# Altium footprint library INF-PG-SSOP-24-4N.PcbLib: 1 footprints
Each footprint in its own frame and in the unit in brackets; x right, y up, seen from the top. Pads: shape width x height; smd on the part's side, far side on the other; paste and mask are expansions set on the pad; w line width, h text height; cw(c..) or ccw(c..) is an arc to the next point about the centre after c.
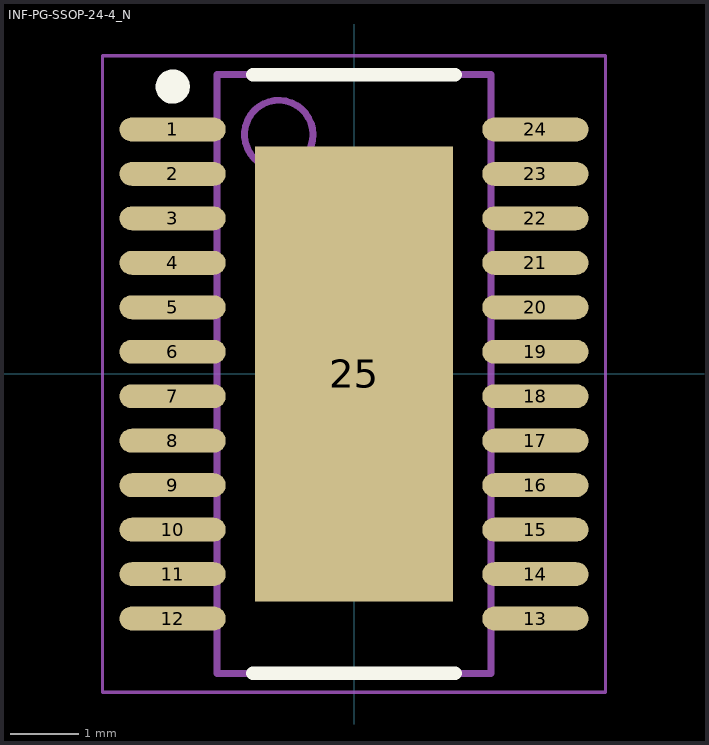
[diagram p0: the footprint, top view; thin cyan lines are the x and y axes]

## INF-PG-SSOP-24-4_N [mm] "SOP, 24-Leads, Body 8.65x3.9mm, Pitch 0.65mm, Thermal Pad 6.65x2.9mm, IPC Medium Density"
height 1.7
pads (25):
  oval 1.55x0.35 smd: 1(-2.65,3.575) 2(-2.65,2.925) 3(-2.65,2.275) 4(-2.65,1.625) 5(-2.65,0.975) 6(-2.65,0.325) 7(-2.65,-0.325) 8(-2.65,-0.975) 9(-2.65,-1.625) 10(-2.65,-2.275) 11(-2.65,-2.925) 12(-2.65,-3.575) 13(2.65,-3.575) 14(2.65,-2.925) 15(2.65,-2.275) 16(2.65,-1.625) 17(2.65,-0.975) 18(2.65,-0.325) 19(2.65,0.325) 20(2.65,0.975) 21(2.65,1.625) 22(2.65,2.275) 23(2.65,2.925) 24(2.65,3.575)
  rect 2.9x6.65 smd: 25(0,0)
Top Overlay:
  circle w0.25: c-2.65,4.2 r0.125
  lines w0.2: -1.475,-4.375 1.475,-4.375 ; -1.475,4.375 1.475,4.375
Mechanical 13:
  circle w0.1: c-1.1,3.5 r0.5
  lines w0.1: -2,-4.375 2,-4.375 2,4.375 -2,4.375 -2,-4.375
Mechanical 15:
  lines w0.05: -3.675,-4.65 3.675,-4.65 3.675,4.65 -3.675,4.65 -3.675,-4.65
  lines w0.1: -0.5,0 0.5,0 ; 0,-0.5 0,0.5
3D body: height 1.7, standoff 0, extent -2,-4.375 2,4.375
